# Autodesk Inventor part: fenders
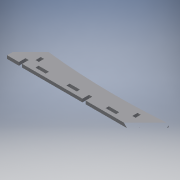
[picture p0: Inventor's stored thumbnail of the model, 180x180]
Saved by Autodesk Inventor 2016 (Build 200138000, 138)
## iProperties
Created: 2017-06
Part Number: fenders
Material: Generic
Document SubType Name: Modeling
Designer: laboratorioesan
Density: 1 g/cm^3
Appearance: Default
Author: laboratorioesan
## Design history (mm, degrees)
sketch "Sketch1"
  geometry: L1 (1057.5, 18.5)-(1117.5, 18.5) reference; L2 (1057.5, 18.5)-(1057.5, 0) reference; L3 (1117.5, 0)-(1057.5, 0) reference; L4 (1117.5, 18.5)-(1117.5, 0) reference; L5 (877.5, 18.5)-(937.5, 18.5) reference; L6 (877.5, 18.5)-(877.5, 0) reference; L7 (937.5, 0)-(877.5, 0) reference; L8 (937.5, 18.5)-(937.5, 0) reference; L9 (649.863, 18.5)-(709.863, 18.5) reference; L10 (649.863, 18.5)-(649.863, 0) reference; L11 (709.863, 0)-(649.863, 0) reference; L12 (709.863, 18.5)-(709.863, 0) reference; L13 (469.863, 18.5)-(529.863, 18.5) reference; L14 (469.863, 18.5)-(469.863, 0) reference; L15 (529.863, 0)-(469.863, 0) reference; L16 (529.863, 18.5)-(529.863, 0) reference; L17 (1117.5, 18.5)-(1550, 18.5) reference; L18 (937.5, 18.5)-(1057.5, 18.5) reference; L19 (709.863, 18.5)-(877.5, 18.5) reference; L20 (529.863, 18.5)-(649.863, 18.5) reference; L21 (0, 18.5)-(469.863, 18.5) reference; L22 (0, 0)-(469.863, 0) reference; L23 (529.863, 0)-(649.863, 0) reference; L24 (709.863, 0)-(877.5, 0) reference; L25 (1137.5, 18.5)-(1137.5, 0) reference; L26 (325.59, -20)-(325.59, 130); L27 (1137.5, 105)-(1137.5, -20); L28 (1012.477, 38.5)-(993.977, 38.5); L29 (993.977, 38.5)-(993.977, 68.5); L30 (993.977, 68.5)-(1012.477, 68.5); L31 (1012.477, 68.5)-(1012.477, 38.5); L32 (451.09, 38.5)-(432.59, 38.5); L33 (432.59, 38.5)-(432.59, 68.5); L34 (432.59, 68.5)-(451.09, 68.5); L35 (451.09, 68.5)-(451.09, 38.5); L36 (394, -17.186)-(394, 18.5) reference; L37 (412.5, -17.186)-(412.5, 18.5) reference; L38 (412.5, -20)-(412.5, 18.5); L39 (412.5, 18.5)-(394, 18.5); L40 (394, 18.5)-(394, -20); L41 (394, -20)-(325.59, -20); L42 (781, 18.5)-(781, -17.186) reference; L43 (762.5, 18.5)-(762.5, -17.186) reference; L44 (781, -20)-(781, 18.5); L45 (781, 18.5)-(762.5, 18.5); L46 (762.5, 18.5)-(762.5, -20); L47 (1137.5, -20)-(781, -20); L48 (762.5, -20)-(412.5, -20); A1 r 3569.02 centre (840.675, 3661.655) between (325.59, 130) and (1137.5, 105)
  constraints: 38 end point, 11 perpendicular, 5 horizontal, 5 parallel, 2 horizontal alignment, 2 point on circle, 1 centre point, 1 collinear, 1 point on line
  dimensions: "d1" = 125 distance of L27.start L27.end; "d2" = 20 horizontal distance of L27.end L3.start; "d3" = 150 distance of L26.end L26.start; "d4" = 18.5 distance of L29.end L30.end; "d5" = 30 distance of L28.end L29.end; "d6" = 20 distance from line of L18 L28.end; "d7" = 18.5 distance of L33.end L34.end; "d8" = 20 distance between parallel lines of L21 L32; "d9" = 107 distance from line of L26 L33.end; "d12" = 30 distance of L32.end L33.end
extrude "Extrusion1" new body sketch "Sketch1" distance "d10" = 18.5; taper "d11" = 0 deg
body "Solid1"
node "Reference1"
node "Reference2"
node "Reference3"
node "Reference4"
node "Reference5"
node "Reference6"
node "Reference7"
node "Reference8"
node "Reference9"
node "Reference10"
node "Reference11"
node "Reference12"
node "Reference13"
node "Reference14"
node "Reference15"
node "Reference16"
node "Reference17"
